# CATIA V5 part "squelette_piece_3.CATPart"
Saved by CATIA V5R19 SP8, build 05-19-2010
Part number: squelette_piece_3
Publications: "Point.5", "Point.4", "Droite.3", "Point.3", "Point.2", "Droite.2", "Point.1", "Point.11", "Droite.1"
Bounding box of the stored display mesh (mm): x -25 to 50, y 381 to 919.812, z -1038.812 to -500
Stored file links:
  G:\EU_thinkMotion\CFAO_2010\SIL_groupe1\SIL_groupe1\A reprendre\lalpha\lalpha\Alpha.mécanisme\squelette_piece_3.CATPart
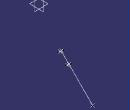
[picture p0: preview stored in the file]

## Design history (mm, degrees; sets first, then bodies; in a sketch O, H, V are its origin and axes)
Set1
  Line1: type PtPt, FirstPoint Point1, SecondPoint DatumPoint1
  Point1: stored without definition
  DatumPoint1
  Line2: type PtPt, FirstPoint Point2, SecondPoint Point3, Start 25, End 25
  Point2: stored without definition
  Point3: stored without definition
  Line3: type PtPt, FirstPoint Point4, SecondPoint Point5, Start 25, End 25
  Point4: stored without definition
  Point5: stored without definition
Body1 (main body)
